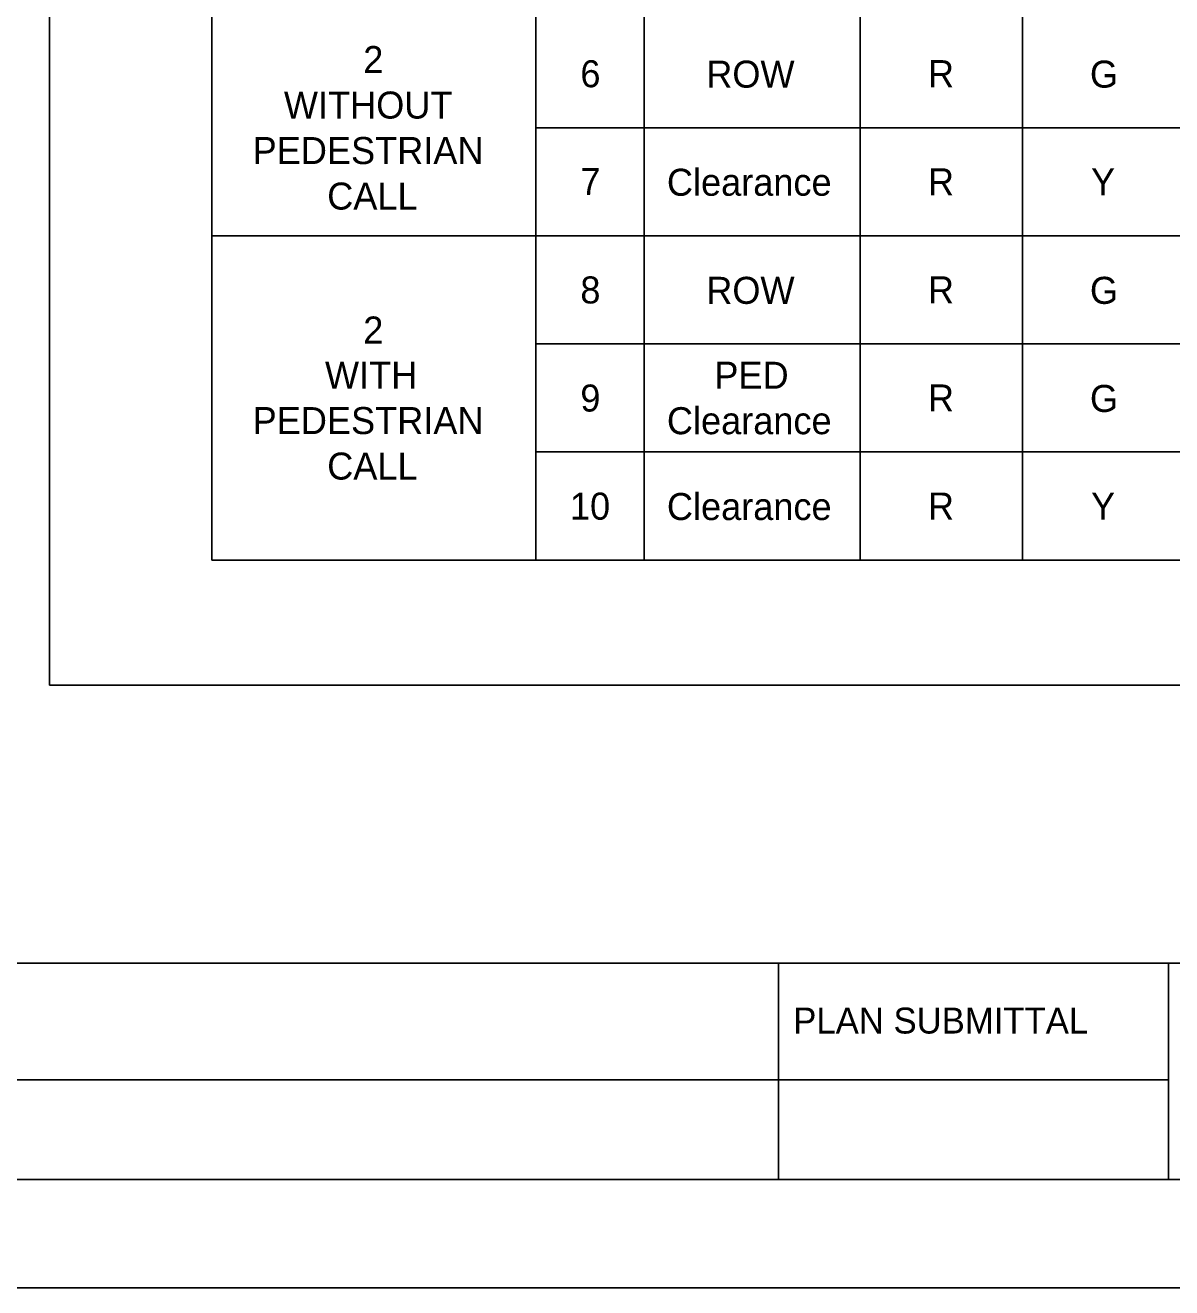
# Model space of a CAD drawing. Extents: x 515543 to 517243, y 660510 to 662861.
# Drawn here: x 516181.2 to 516446.4, y 661760.7 to 662052.7 of the extents above; entities that cross this region are included whole.
import ezdxf

# ---------------------------------------------------------------- set-up
doc = ezdxf.new("R2010")
doc.units = 0
for name, color, linetype in [('ANNO-TXT', 7, 'Continuous'), ('Default', 7, 'Continuous'), ('Level 62', 7, 'Continuous'), ('SHT-BDR', 7, 'Continuous'), ('SHT-BNDRY', 7, 'Continuous')]:
    doc.layers.add(name, color=color, linetype=linetype)

msp = doc.modelspace()

# ---------------------------------------------------------------- linework, layer by layer
at = {"layer": 'Default'}
for p, q in [((516186.87, 662735.88), (516186.87, 661900.05)), ((516224.37, 662204), (516224.37, 661929)), ((516299.37, 662204), (516299.37, 661929)), ((516324.37, 662204), (516324.37, 661929)), ((516374.37, 662204), (516374.37, 661929)), ((516411.87, 662204), (516411.87, 661929)), ((516299.37, 662029), (516486.87, 662029)), ((516224.37, 662004), (516449.37, 662004)), ((516224.37, 662004), (516449.37, 662004)), ((516299.37, 661979), (516486.87, 661979)), ((516299.37, 661954), (516449.37, 661954)), ((516224.37, 661929), (516599.37, 661929)), ((516186.87, 661900.05), (516636.87, 661900.05))]:
    msp.add_line(p, q, dxfattribs=at)
at = {"layer": 'Level 62'}
msp.add_lwpolyline([(515542.51, 661760.72), (517242.52, 661760.72), (517242.52, 662860.72), (515542.51, 662860.72)], close=True, dxfattribs=at)
at = {"layer": 'SHT-BDR'}
msp.add_lwpolyline([(515667.5, 661835.77), (517167.5, 661835.77), (517167.5, 662785.77), (515667.5, 662785.77)], close=True, dxfattribs=at)
at = {"layer": 'SHT-BNDRY'}
for p, q in [((516355.45, 661785.72), (516355.45, 661835.77)), ((516445.64, 661785.72), (516445.64, 661835.77)), ((515667.5, 661808.77), (516445.64, 661808.77))]:
    msp.add_line(p, q, dxfattribs=at)
msp.add_lwpolyline([(515605.01, 661785.72), (517217.52, 661785.72), (517217.52, 662835.72), (515605.01, 662835.72)], close=True, dxfattribs=at)

# ---------------------------------------------------------------- texts
at = {"layer": 'ANNO-TXT'}
msp.add_text('PLAN SUBMITTAL', height=6, rotation=360, dxfattribs=at).set_placement((516358.87, 661819.51))
at = {"layer": 'Default'}
for s, p in [('2', (516259.41, 662041.63)), ('6', (516309.64, 662038.35)), ('ROW', (516338.75, 662038.26)), ('R', (516390.02, 662038.37)), ('G', (516427.49, 662038.26)), ('WITHOUT ', (516241.06, 662031.11)), ('PEDESTRIAN', (516233.83, 662020.59)), ('7', (516309.64, 662013.45)), ('Clearance', (516329.65, 662013.26)), ('R', (516390.02, 662013.37)), ('Y', (516427.74, 662013.37)), ('CALL', (516251.08, 662010.06)), ('8', (516309.63, 661988.35)), ('ROW', (516338.75, 661988.26)), ('R', (516390.02, 661988.37)), ('G', (516427.49, 661988.26)), ('2', (516259.41, 661979.08)), ('WITH', (516250.56, 661968.66)), ('PED', (516340.62, 661968.63)), ('9', (516309.63, 661963.35)), ('R', (516390.02, 661963.37)), ('G', (516427.49, 661963.26)), ('Clearance', (516329.65, 661958.11)), ('PEDESTRIAN', (516233.83, 661958.14)), ('CALL', (516251.08, 661947.62)), ('10', (516307.22, 661938.35)), ('Clearance', (516329.65, 661938.26)), ('R', (516390.02, 661938.37)), ('Y', (516427.74, 661938.37))]:
    msp.add_text(s, height=6.25, dxfattribs=at).set_placement(p)

doc.saveas('drawing.dxf')
